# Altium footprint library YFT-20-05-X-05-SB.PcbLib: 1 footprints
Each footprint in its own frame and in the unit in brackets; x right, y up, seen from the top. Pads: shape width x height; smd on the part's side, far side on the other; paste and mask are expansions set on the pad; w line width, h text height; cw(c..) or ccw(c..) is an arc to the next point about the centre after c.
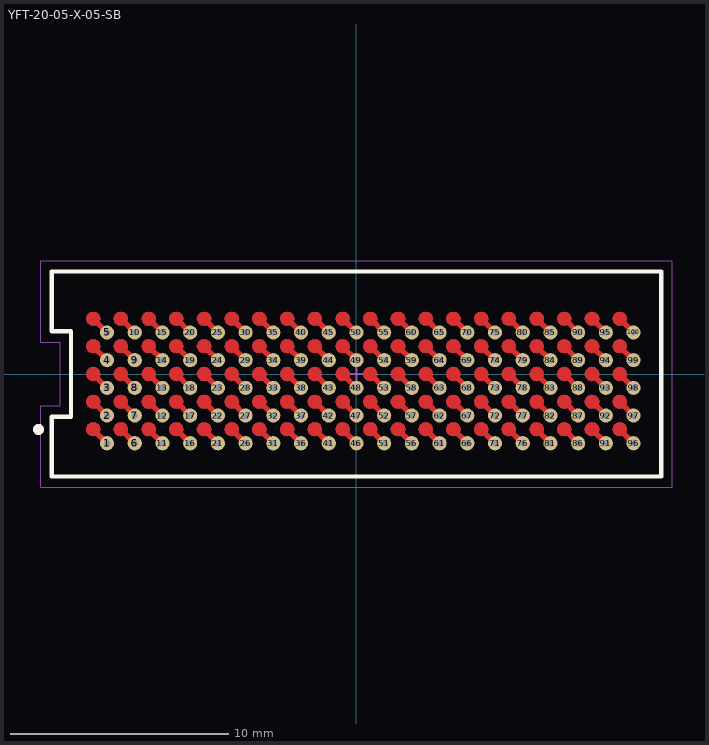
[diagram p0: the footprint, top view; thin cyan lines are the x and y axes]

## YFT-20-05-X-05-SB [mm] "1.27mm pitch, 100 pin, header array; 5 rows, SMT"
height 4.5
pads (100):
  round 0.65 hole 0.3 unplated mask+0: 1(-11.43,-3.175) 2(-11.43,-1.905) 3(-11.43,-0.635) 4(-11.43,0.635) 5(-11.43,1.905) 6(-10.16,-3.175) 7(-10.16,-1.905) 8(-10.16,-0.635) 9(-10.16,0.635) 10(-10.16,1.905) 11(-8.89,-3.175) 12(-8.89,-1.905) 13(-8.89,-0.635) 14(-8.89,0.635) 15(-8.89,1.905) 16(-7.62,-3.175) 17(-7.62,-1.905) 18(-7.62,-0.635) 19(-7.62,0.635) 20(-7.62,1.905) 21(-6.35,-3.175) 22(-6.35,-1.905) 23(-6.35,-0.635) 24(-6.35,0.635) 25(-6.35,1.905) 26(-5.08,-3.175) 27(-5.08,-1.905) 28(-5.08,-0.635) 29(-5.08,0.635) 30(-5.08,1.905) 31(-3.81,-3.175) 32(-3.81,-1.905) 33(-3.81,-0.635) 34(-3.81,0.635) 35(-3.81,1.905) 36(-2.54,-3.175) 37(-2.54,-1.905) 38(-2.54,-0.635) 39(-2.54,0.635) 40(-2.54,1.905) 41(-1.27,-3.175) 42(-1.27,-1.905) 43(-1.27,-0.635) 44(-1.27,0.635) 45(-1.27,1.905) 46(0,-3.175) 47(0,-1.905) 48(0,-0.635) 49(0,0.635) 50(0,1.905) 51(1.27,-3.175) 52(1.27,-1.905) 53(1.27,-0.635) 54(1.27,0.635) 55(1.27,1.905) 56(2.54,-3.175) 57(2.54,-1.905) 58(2.54,-0.635) 59(2.54,0.635) 60(2.54,1.905) 61(3.81,-3.175) 62(3.81,-1.905) 63(3.81,-0.635) 64(3.81,0.635) 65(3.81,1.905) 66(5.08,-3.175) 67(5.08,-1.905) 68(5.08,-0.635) 69(5.08,0.635) 70(5.08,1.905) 71(6.35,-3.175) 72(6.35,-1.905) 73(6.35,-0.635) 74(6.35,0.635) 75(6.35,1.905) 76(7.62,-3.175) 77(7.62,-1.905) 78(7.62,-0.635) 79(7.62,0.635) 80(7.62,1.905) 81(8.89,-3.175) 82(8.89,-1.905) 83(8.89,-0.635) 84(8.89,0.635) 85(8.89,1.905) 86(10.16,-3.175) 87(10.16,-1.905) 88(10.16,-0.635) 89(10.16,0.635) 90(10.16,1.905) 91(11.43,-3.175) 92(11.43,-1.905) 93(11.43,-0.635) 94(11.43,0.635) 95(11.43,1.905) 96(12.7,-3.175) 97(12.7,-1.905) 98(12.7,-0.635) 99(12.7,0.635) 100(12.7,1.905)
Top Layer:
  drawing of 200 lines, arcs and shapes, not listed
Top Overlay:
  circle w0.25: c-14.57,-2.54 r0.125
  lines w0.2: -13.97,-4.699 -13.97,-1.956 -13.081,-1.956 -13.081,1.956 -13.97,1.956 -13.97,4.699 13.97,4.699 13.97,-4.699 -13.97,-4.699
Top Paste:
  drawing of 100 lines, arcs and shapes, not listed
Top Solder:
  drawing of 100 lines, arcs and shapes, not listed
Mechanical 12:
  lines w0.001: -13.97,-4.699 -13.97,-1.956 -13.081,-1.956 -13.081,1.956 -13.97,1.956 -13.97,4.699 13.97,4.699 13.97,-4.699 -13.97,-4.699
Mechanical 13:
  drawing of 110 lines, arcs and shapes, not listed
  text ".Designator" at 0,0 h1.52
Mechanical 15:
  lines w0.005: -14.47,-5.199 14.47,-5.199 14.47,5.199 -14.47,5.199 -14.47,1.456 -13.581,1.456 -13.581,-1.456 -14.47,-1.456 -14.47,-5.199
